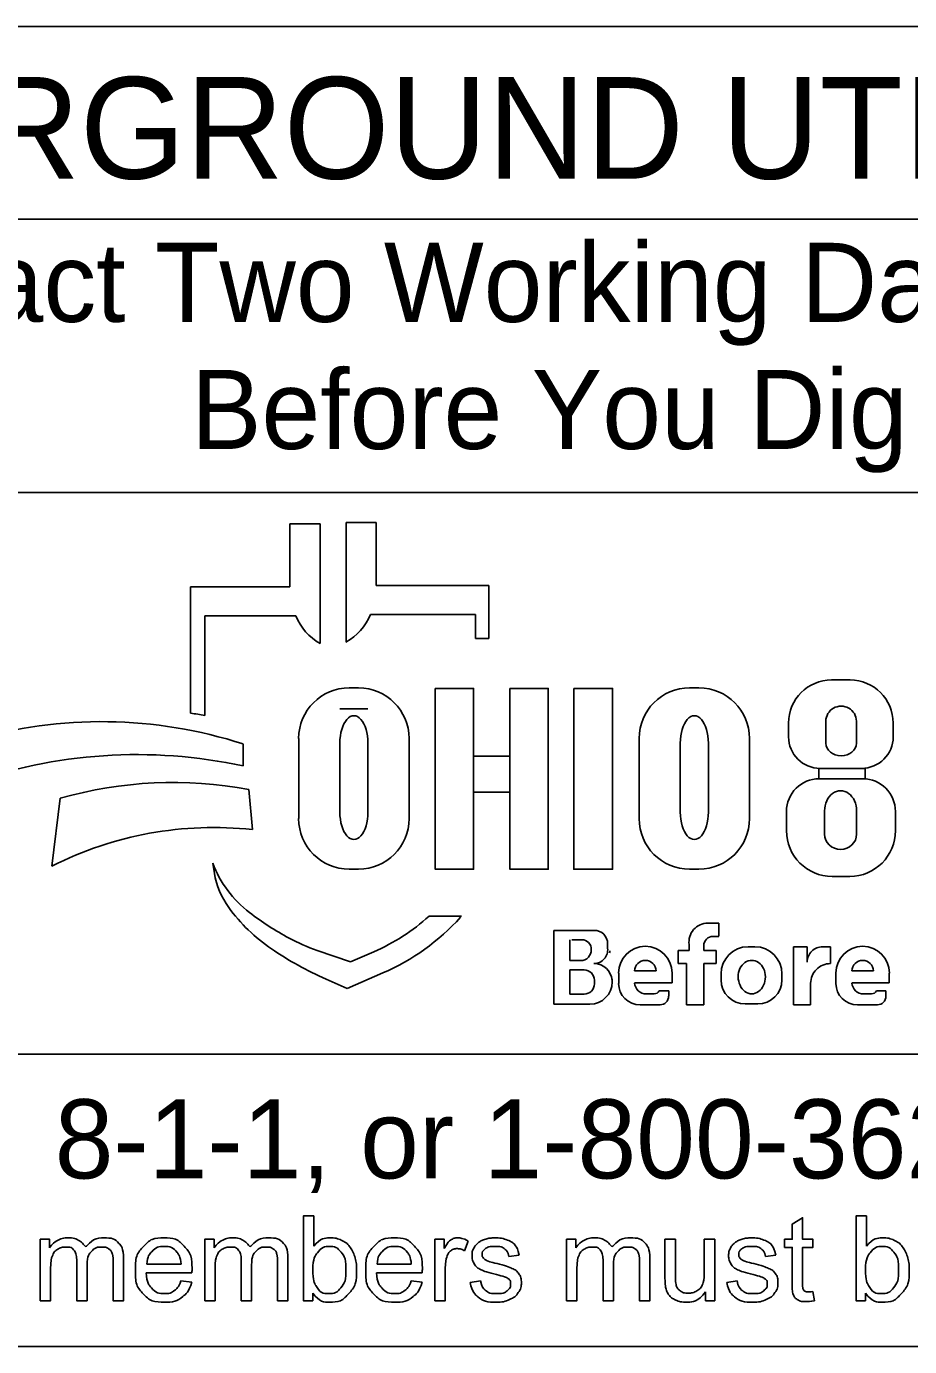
# Model space of a CAD drawing. Extents: x 0 to 34, y 0 to 22.
# Drawn here: x 3.267 to 4.831, y 2.143 to 4.48 of the extents above; entities that cross this region are included whole.
import ezdxf

# ---------------------------------------------------------------- set-up
doc = ezdxf.new("R2010")
doc.units = 0
doc.layers.add('SH_Data', color=7, linetype='Continuous')
doc.layers.add('SH_Text', color=7, linetype='Continuous')

msp = doc.modelspace()

# ---------------------------------------------------------------- linework, layer by layer
at = {"layer": 'SH_Data'}
for p, q in [((6.6275, 4.4803), (2.3775, 4.4803)), ((2.3775, 4.1387), (6.6275, 4.1387)), ((2.3775, 3.6553), (6.6275, 3.6553)), ((6.6275, 2.6607), (2.3775, 2.6607)), ((6.6275, 2.1428), (2.3775, 2.1428))]:
    msp.add_line(p, q, dxfattribs=at)
at = {"layer": 'SH_Text'}
for p, q in [((3.7335, 3.4883), (3.7335, 3.5998)), ((3.7335, 3.5998), (3.7872, 3.5998)), ((3.7872, 3.5998), (3.7872, 3.3877)), ((3.8329, 3.39), (3.8329, 3.6021)), ((3.8329, 3.6021), (3.8865, 3.6021)), ((3.8865, 3.6021), (3.8865, 3.4906)), ((3.5576, 3.2644), (3.5576, 3.4883)), ((3.5576, 3.4883), (3.7335, 3.4883)), ((3.8865, 3.4906), (4.0857, 3.4906)), ((4.0857, 3.4906), (4.0857, 3.3968)), ((3.5828, 3.4369), (3.5828, 3.26)), ((3.7439, 3.4369), (3.5828, 3.4369)), ((4.0625, 3.4392), (3.8761, 3.4392)), ((4.0625, 3.3968), (4.0625, 3.4392)), ((4.0857, 3.3968), (4.0625, 3.3968)), ((4.6931, 3.3231), (4.7258, 3.3231)), ((3.8385, 3.3091), (3.8551, 3.3091)), ((4.4416, 3.3091), (4.4581, 3.3091)), ((3.8718, 3.2721), (3.822, 3.2721)), ((4.683, 3.2111), (4.683, 3.2504)), ((4.7371, 3.2504), (4.7371, 3.2111)), ((4.6168, 3.2225), (4.6168, 3.2468)), ((4.8022, 3.2468), (4.8022, 3.2225)), ((3.6509, 3.2097), (3.6509, 3.1709)), ((3.7491, 3.0776), (3.7491, 3.2196)), ((3.822, 3.089), (3.822, 3.2114)), ((3.8718, 3.2114), (3.8718, 3.089)), ((3.9445, 3.2196), (3.9445, 3.0776)), ((4.3521, 3.0776), (4.3521, 3.2196)), ((4.425, 3.089), (4.425, 3.2114)), ((4.4748, 3.2114), (4.4748, 3.089)), ((4.5476, 3.2196), (4.5476, 3.0776)), ((4.7462, 3.1665), (4.6728, 3.1665)), ((4.671, 3.1482), (4.7483, 3.1482)), ((3.312, 2.9936), (3.3267, 3.1137)), ((3.6608, 3.1291), (3.6671, 3.0582)), ((4.6131, 3.0563), (4.6131, 3.0903)), ((4.6806, 3.0503), (4.6806, 3.0912)), ((4.7374, 3.0912), (4.7374, 3.0503)), ((4.8062, 3.0903), (4.8062, 3.0563)), ((3.5997, 2.9807), (3.5967, 2.9986)), ((3.8551, 2.9882), (3.8385, 2.9882)), ((4.4581, 2.9882), (4.4416, 2.9882)), ((4.7252, 2.9753), (4.6941, 2.9753)), ((3.98, 2.9048), (4.0375, 2.9048)), ((4.2013, 2.749), (4.2013, 2.8798)), ((4.2013, 2.8798), (4.2725, 2.8798)), ((4.4739, 2.8926), (4.4934, 2.8926)), ((4.4934, 2.8926), (4.4934, 2.8696)), ((4.2293, 2.8263), (4.2293, 2.8632)), ((4.2545, 2.8632), (4.2332, 2.8632)), ((4.2963, 2.856), (4.2963, 2.8481)), ((4.4406, 2.8442), (4.4406, 2.8546)), ((4.4667, 2.8526), (4.4667, 2.8442)), ((4.4934, 2.8691), (4.4832, 2.8691)), ((3.7816, 2.8444), (3.841, 2.8239)), ((3.841, 2.8239), (3.8821, 2.8417)), ((4.4213, 2.8212), (4.4213, 2.8442)), ((4.4213, 2.8442), (4.4406, 2.8442)), ((4.4667, 2.8442), (4.4883, 2.8442)), ((4.4883, 2.8442), (4.4883, 2.8212)), ((4.5451, 2.8508), (4.5573, 2.8508)), ((4.6254, 2.7478), (4.6254, 2.8505)), ((4.6254, 2.8505), (4.6499, 2.8505)), ((4.6499, 2.8505), (4.6499, 2.8237)), ((4.6772, 2.8505), (4.691, 2.8505)), ((4.691, 2.8505), (4.691, 2.8209)), ((4.2487, 2.8263), (4.2293, 2.8263)), ((4.2293, 2.7669), (4.2293, 2.8097)), ((4.2293, 2.8097), (4.2548, 2.8097)), ((4.3824, 2.8082), (4.3439, 2.8082)), ((4.4362, 2.8212), (4.4213, 2.8212)), ((4.4362, 2.7478), (4.4362, 2.8212)), ((4.4883, 2.8212), (4.4667, 2.8212)), ((4.4667, 2.8212), (4.4667, 2.7478)), ((4.7674, 2.8082), (4.7288, 2.8082)), ((3.835, 2.7769), (3.7976, 2.7934)), ((3.8983, 2.8044), (3.835, 2.7769)), ((4.2729, 2.7916), (4.2729, 2.7853)), ((4.3043, 2.7887), (4.3043, 2.7884)), ((4.3159, 2.7858), (4.3159, 2.8042)), ((4.4104, 2.7866), (4.344, 2.7866)), ((4.4104, 2.8042), (4.4104, 2.7866)), ((4.4973, 2.7922), (4.4973, 2.8029)), ((4.6051, 2.8029), (4.6051, 2.7922)), ((4.6559, 2.786), (4.6559, 2.7478)), ((4.7008, 2.7858), (4.7008, 2.8042)), ((4.7953, 2.7866), (4.7289, 2.7866)), ((4.7953, 2.8042), (4.7953, 2.7866)), ((4.2546, 2.7669), (4.2293, 2.7669)), ((4.3649, 2.7673), (4.379, 2.7673)), ((4.3876, 2.7729), (4.4045, 2.7729)), ((4.4045, 2.7729), (4.4045, 2.7631)), ((4.7498, 2.7673), (4.7639, 2.7673)), ((4.7725, 2.7729), (4.7894, 2.7729)), ((4.7894, 2.7729), (4.7894, 2.7631)), ((4.265, 2.749), (4.2013, 2.749)), ((4.3892, 2.7478), (4.3538, 2.7478)), ((4.4667, 2.7478), (4.4362, 2.7478)), ((4.5623, 2.7494), (4.5401, 2.7494)), ((4.6559, 2.7478), (4.6254, 2.7478)), ((4.7742, 2.7478), (4.7388, 2.7478))]:
    msp.add_line(p, q, dxfattribs=at)
for points in [[(3.991, 3.3081), (4.0589, 3.3081), (4.0589, 2.9881), (3.991, 2.9881)], [(4.1231, 3.3081), (4.1911, 3.3081), (4.1911, 2.9881), (4.1231, 2.9881)], [(4.2364, 3.3081), (4.3052, 3.3081), (4.3052, 2.9881), (4.2364, 2.9881)], [(4.0589, 3.1882), (4.1231, 3.1882), (4.1231, 3.1242), (4.0589, 3.1242)], [(4.6706, 3.1665), (4.7523, 3.1665), (4.7523, 3.1481), (4.6706, 3.1481)]]:
    msp.add_lwpolyline(points, close=True, dxfattribs=at)
for points in [[(3.7743, 2.2239), (3.7573, 2.2239), (3.7573, 2.3741), (3.7757, 2.3741), (3.7757, 2.3206)], [(4.6233, 2.2558), (4.6233, 2.3185), (4.6097, 2.3185), (4.6097, 2.3328), (4.6233, 2.3328), (4.6233, 2.3597), (4.6417, 2.3708), (4.6417, 2.3328), (4.6601, 2.3328), (4.6601, 2.3185), (4.6417, 2.3185), (4.6417, 2.2547)], [(4.7534, 2.2239), (4.7363, 2.2239), (4.7363, 2.3741), (4.7548, 2.3741), (4.7548, 2.3206)], [(3.2912, 2.2239), (3.2912, 2.3328), (3.3077, 2.3328), (3.3077, 2.3174)], [(3.5826, 2.2239), (3.5826, 2.3328), (3.5991, 2.3328), (3.5991, 2.3174)], [(3.9904, 2.2239), (3.9904, 2.3328), (4.007, 2.3328), (4.007, 2.3163)], [(4.0495, 2.3293), (4.043, 2.3122)], [(4.2236, 2.2239), (4.2236, 2.3328), (4.2401, 2.3328), (4.2401, 2.3174)], [(4.3979, 2.2654), (4.3979, 2.3328), (4.4164, 2.3328), (4.4164, 2.2724)], [(4.4676, 2.2745), (4.4676, 2.3328), (4.4861, 2.3328), (4.4861, 2.2239), (4.4696, 2.2239)], [(3.3743, 2.2871), (3.3743, 2.2239), (3.3559, 2.2239), (3.3559, 2.2946)], [(3.4388, 2.2986), (3.4388, 2.2239), (3.4203, 2.2239), (3.4203, 2.2924)], [(3.6657, 2.2871), (3.6657, 2.2239), (3.6473, 2.2239), (3.6473, 2.2946)], [(3.7301, 2.2986), (3.7301, 2.2239), (3.7117, 2.2239), (3.7117, 2.2924)], [(4.1394, 2.3046), (4.1213, 2.3022)], [(4.3067, 2.2871), (4.3067, 2.2239), (4.2883, 2.2239), (4.2883, 2.2946)], [(4.3711, 2.2986), (4.3711, 2.2239), (4.3527, 2.2239), (4.3527, 2.2924)], [(4.594, 2.3046), (4.5759, 2.3022)], [(3.3097, 2.2803), (3.3097, 2.2239), (3.2912, 2.2239)], [(3.56, 2.2736), (3.4788, 2.2736)], [(3.4799, 2.2887), (3.5406, 2.2887)], [(3.601, 2.2803), (3.601, 2.2239), (3.5826, 2.2239)], [(3.968, 2.2736), (3.8868, 2.2736)], [(3.8879, 2.2887), (3.9486, 2.2887)], [(4.0088, 2.2809), (4.0088, 2.2239), (3.9904, 2.2239)], [(4.242, 2.2803), (4.242, 2.2239), (4.2236, 2.2239)], [(3.5404, 2.2591), (3.5595, 2.2567)], [(3.9484, 2.2591), (3.9675, 2.2567)], [(4.053, 2.2564), (4.0712, 2.2593)], [(4.5076, 2.2564), (4.5258, 2.2593)], [(3.7743, 2.2375), (3.7743, 2.2239)], [(4.4696, 2.2239), (4.4696, 2.24)], [(4.6601, 2.2404), (4.6628, 2.2241)], [(4.7534, 2.2375), (4.7534, 2.2239)]]:
    msp.add_lwpolyline(points, dxfattribs=at)
for centre, radius, start, end in [((3.8353, 3.4736), 0.0985, 201.9296, 240.7469), ((3.7847, 3.476), 0.0985, 299.2531, 338.0704), ((4.6931, 3.2468), 0.0763, 90, 180), ((4.7258, 3.2468), 0.0763, 0, 90), ((3.8385, 3.2196), 0.0895, 90, 180), ((3.8551, 3.2196), 0.0895, 0, 90), ((4.4416, 3.2196), 0.0895, 90, 180), ((4.4581, 3.2196), 0.0895, 0, 90), ((3.3997, 2.4302), 0.8191, 72.1402, 106.3144), ((3.4295, 2.4554), 0.8191, 79.2074, 81.0007), ((4.6728, 3.2225), 0.056, 180, 270), ((4.7462, 3.2225), 0.056, 270, 0), ((3.4628, 2.2991), 0.8919, 77.8238, 109.8274), ((3.5267, 2.4094), 0.7322, 79.44, 105.8467), ((4.671, 3.0903), 0.0579, 90, 180), ((4.7483, 3.0903), 0.0579, 0, 90), ((3.8385, 3.0776), 0.0895, 180, 270), ((3.8551, 3.0776), 0.0895, 270, 0), ((4.4416, 3.0776), 0.0895, 180, 270), ((4.4581, 3.0776), 0.0895, 270, 0), ((3.5987, 2.4262), 0.6357, 83.8248, 116.8021), ((4.6941, 3.0563), 0.081, 180, 270), ((4.7252, 3.0563), 0.081, 270, 0), ((3.7841, 3.0707), 0.2008, 201.0457, 232.5314), ((3.741, 3.0048), 0.1433, 189.6817, 216.0884), ((3.8747, 3.1022), 0.3088, 216.0884, 235.7167), ((3.9766, 3.3219), 0.5173, 232.5314, 241.794), ((3.7387, 3.1722), 0.3602, 293.4582, 312.0712), ((3.7387, 3.1722), 0.401, 293.4582, 317.8286), ((4.2725, 2.856), 0.0238, 0, 90), ((4.4739, 2.859), 0.0335, 90, 187.5187), ((3.8914, 3.1631), 0.3371, 241.794, 250.9821), ((4.2505, 2.8463), 0.0169, 357.8325, 90), ((4.4832, 2.8526), 0.0165, 90, 180), ((4.0412, 3.3465), 0.6044, 235.7167, 246.2325), ((4.2487, 2.845), 0.0187, 270, 2.0582), ((4.2721, 2.8453), 0.0243, 270, 6.6529), ((4.2827, 2.8438), 0.0175, 347.4023, 0), ((4.3631, 2.8042), 0.0473, 0, 180), ((4.5451, 2.8029), 0.0478, 90, 180), ((4.5573, 2.8029), 0.0478, 0, 90), ((4.6768, 2.8237), 0.0269, 89.2449, 180), ((4.7481, 2.8042), 0.0473, 0, 180), ((4.2548, 2.7916), 0.0181, 0, 90), ((4.2722, 2.7889), 0.0321, 4.0748, 90), ((4.3632, 2.8072), 0.0193, 2.9632, 177.0368), ((4.6908, 2.786), 0.0349, 89.6033, 180), ((4.7481, 2.8072), 0.0193, 2.9632, 177.0368), ((4.2546, 2.7853), 0.0184, 270, 0), ((4.265, 2.7884), 0.0393, 270, 0), ((4.2714, 2.7887), 0.033, 0, 11.7502), ((4.3538, 2.7858), 0.038, 180, 270), ((4.3649, 2.7883), 0.021, 184.827, 270), ((4.5401, 2.7922), 0.0428, 180, 270), ((4.5623, 2.7922), 0.0428, 270, 0), ((4.7388, 2.7858), 0.038, 180, 270), ((4.7498, 2.7883), 0.021, 184.827, 270), ((4.379, 2.7767), 0.00938, 270, 335.9979), ((4.3892, 2.7631), 0.0152, 270, 0), ((4.7639, 2.7767), 0.00938, 270, 335.9979), ((4.7742, 2.7631), 0.0152, 270, 0)]:
    msp.add_arc(centre, radius, start, end, dxfattribs=at)
for centre, major_axis, ratio, start_param, end_param in [((4.71, 3.2504), (0.0271, 0), 0.969373, 0, 3.141593), ((3.8469, 3.2114), (0, 0.0484), 0.514403, 4.712389, 7.853982), ((4.4499, 3.2114), (0, 0.0484), 0.514403, 4.712389, 7.853982), ((4.71, 3.2111), (0.0271, 0), 0.818453, 3.141593, 6.283185), ((4.709, 3.0912), (0, 0.0358), 0.794529, 4.712389, 7.853982), ((3.8469, 3.089), (0, 0.0484), 0.514403, 1.570796, 4.712389), ((4.4499, 3.089), (0, 0.0484), 0.514403, 1.570796, 4.712389), ((4.709, 3.0503), (0.0284, 0), 0.959837, 3.141593, 6.283185), ((4.5517, 2.7976), (0, 0.029), 0.832186, 4.712389, 7.853982), ((4.5517, 2.7976), (0, 0.0302), 0.797287, 1.570796, 4.712389)]:
    msp.add_ellipse(centre, major_axis=major_axis, ratio=ratio, start_param=start_param, end_param=end_param, dxfattribs=at)
for points in [[(3.3077, 2.3174), (3.3128, 2.3254), (3.3214, 2.3303), (3.3299, 2.3352), (3.3407, 2.3352), (3.3528, 2.3352), (3.3606, 2.3301), (3.3683, 2.3251), (3.3715, 2.3161), (3.3844, 2.3352), (3.4051, 2.3352), (3.4213, 2.3352), (3.43, 2.3262), (3.4388, 2.3172), (3.4388, 2.2986)], [(3.3559, 2.2946), (3.3559, 2.3069), (3.3514, 2.313), (3.3469, 2.3191), (3.3366, 2.3191), (3.3288, 2.3191), (3.3222, 2.315), (3.3156, 2.311), (3.3126, 2.3031), (3.3097, 2.2952), (3.3097, 2.2803)], [(3.4203, 2.2924), (3.4203, 2.3035), (3.4185, 2.3083), (3.4168, 2.3132), (3.412, 2.3162), (3.4073, 2.3191), (3.401, 2.3191), (3.3895, 2.3191), (3.3819, 2.3115), (3.3743, 2.3039), (3.3743, 2.2871)], [(3.5595, 2.2567), (3.555, 2.24), (3.5428, 2.2307), (3.5306, 2.2215), (3.5117, 2.2215), (3.4878, 2.2215), (3.4738, 2.2362), (3.4598, 2.2509), (3.4598, 2.2774), (3.4598, 2.3049), (3.474, 2.32), (3.4881, 2.3352), (3.5106, 2.3352), (3.5324, 2.3352), (3.5463, 2.3203), (3.5601, 2.3055), (3.5601, 2.2785), (3.5601, 2.2769), (3.56, 2.2736)], [(3.5406, 2.2887), (3.5394, 2.3025), (3.5337, 2.3094), (3.5249, 2.3201), (3.5108, 2.3201), (3.4981, 2.3201), (3.4894, 2.3115), (3.4808, 2.303), (3.4799, 2.2887)], [(3.5991, 2.3174), (3.6042, 2.3254), (3.6127, 2.3303), (3.6212, 2.3352), (3.6321, 2.3352), (3.6442, 2.3352), (3.6519, 2.3301), (3.6597, 2.3251), (3.6628, 2.3161), (3.6758, 2.3352), (3.6965, 2.3352), (3.7127, 2.3352), (3.7214, 2.3262), (3.7301, 2.3172), (3.7301, 2.2986)], [(3.6473, 2.2946), (3.6473, 2.3069), (3.6428, 2.313), (3.6383, 2.3191), (3.628, 2.3191), (3.6202, 2.3191), (3.6136, 2.315), (3.607, 2.311), (3.604, 2.3031), (3.601, 2.2952), (3.601, 2.2803)], [(3.7117, 2.2924), (3.7117, 2.3035), (3.7099, 2.3083), (3.7081, 2.3132), (3.7034, 2.3162), (3.6987, 2.3191), (3.6923, 2.3191), (3.6809, 2.3191), (3.6733, 2.3115), (3.6657, 2.3039), (3.6657, 2.2871)], [(3.7741, 2.2792), (3.7741, 2.2596), (3.7794, 2.2509), (3.7881, 2.2366), (3.8029, 2.2366), (3.815, 2.2366), (3.8238, 2.2471), (3.8326, 2.2576), (3.8326, 2.2784), (3.8326, 2.2998), (3.8241, 2.3099), (3.8157, 2.3201), (3.8038, 2.3201), (3.7917, 2.3201), (3.7829, 2.3096), (3.7741, 2.299), (3.7741, 2.2792)], [(3.7757, 2.3206), (3.7874, 2.3352), (3.8055, 2.3352), (3.8155, 2.3352), (3.8245, 2.3311), (3.8335, 2.3271), (3.8392, 2.3198), (3.845, 2.3124), (3.8483, 2.3021), (3.8516, 2.2918), (3.8516, 2.28), (3.8516, 2.252), (3.8378, 2.2368), (3.8239, 2.2215), (3.8046, 2.2215), (3.7853, 2.2215), (3.7743, 2.2375)], [(3.9675, 2.2567), (3.963, 2.24), (3.9508, 2.2307), (3.9386, 2.2215), (3.9196, 2.2215), (3.8958, 2.2215), (3.8818, 2.2362), (3.8678, 2.2509), (3.8678, 2.2774), (3.8678, 2.3049), (3.882, 2.32), (3.8961, 2.3352), (3.9186, 2.3352), (3.9404, 2.3352), (3.9543, 2.3203), (3.9681, 2.3055), (3.9681, 2.2785), (3.9681, 2.2769), (3.968, 2.2736)], [(3.9486, 2.2887), (3.9474, 2.3025), (3.9417, 2.3094), (3.9328, 2.3201), (3.9188, 2.3201), (3.9061, 2.3201), (3.8974, 2.3115), (3.8888, 2.303), (3.8879, 2.2887)], [(4.007, 2.3163), (4.0133, 2.3278), (4.0187, 2.3315), (4.0241, 2.3352), (4.0305, 2.3352), (4.0398, 2.3352), (4.0495, 2.3293)], [(4.043, 2.3122), (4.0363, 2.3162), (4.0295, 2.3162), (4.0235, 2.3162), (4.0187, 2.3125), (4.0139, 2.3089), (4.0119, 2.3024), (4.0088, 2.2926), (4.0088, 2.2809)], [(4.1213, 2.3022), (4.1201, 2.3106), (4.1142, 2.3153), (4.1083, 2.3201), (4.0975, 2.3201), (4.0848, 2.3201), (4.0794, 2.3159), (4.0739, 2.3116), (4.0739, 2.306), (4.0739, 2.3024), (4.0762, 2.2995), (4.0785, 2.2966), (4.0833, 2.2946), (4.086, 2.2936), (4.0996, 2.2899), (4.1192, 2.2847), (4.1269, 2.2813), (4.1347, 2.278), (4.1391, 2.2717), (4.1435, 2.2653), (4.1435, 2.2559), (4.1435, 2.2467), (4.1381, 2.2386), (4.1327, 2.2304), (4.1226, 2.226), (4.1124, 2.2215), (4.0996, 2.2215), (4.0784, 2.2215), (4.0672, 2.2303), (4.0561, 2.2391), (4.053, 2.2564)], [(4.0712, 2.2593), (4.0727, 2.2483), (4.0798, 2.2425), (4.0868, 2.2366), (4.0995, 2.2366), (4.1122, 2.2366), (4.1184, 2.2418), (4.1245, 2.247), (4.1245, 2.254), (4.1245, 2.2602), (4.1191, 2.2638), (4.1153, 2.2663), (4.1002, 2.2701), (4.0799, 2.2752), (4.072, 2.2789), (4.0642, 2.2827), (4.0601, 2.2893), (4.0561, 2.2959), (4.0561, 2.3038), (4.0561, 2.3111), (4.0594, 2.3173), (4.0628, 2.3235), (4.0685, 2.3276), (4.0728, 2.3308), (4.0803, 2.333), (4.0877, 2.3352), (4.0962, 2.3352), (4.109, 2.3352), (4.1187, 2.3315), (4.1284, 2.3278), (4.133, 2.3215), (4.1377, 2.3152), (4.1394, 2.3046)], [(4.2401, 2.3174), (4.2452, 2.3254), (4.2537, 2.3303), (4.2622, 2.3352), (4.2731, 2.3352), (4.2852, 2.3352), (4.2929, 2.3301), (4.3007, 2.3251), (4.3038, 2.3161), (4.3168, 2.3352), (4.3375, 2.3352), (4.3537, 2.3352), (4.3624, 2.3262), (4.3711, 2.3172), (4.3711, 2.2986)], [(4.2883, 2.2946), (4.2883, 2.3069), (4.2838, 2.313), (4.2793, 2.3191), (4.269, 2.3191), (4.2612, 2.3191), (4.2546, 2.315), (4.248, 2.311), (4.245, 2.3031), (4.242, 2.2952), (4.242, 2.2803)], [(4.3527, 2.2924), (4.3527, 2.3035), (4.3509, 2.3083), (4.3491, 2.3132), (4.3444, 2.3162), (4.3397, 2.3191), (4.3333, 2.3191), (4.3219, 2.3191), (4.3143, 2.3115), (4.3067, 2.3039), (4.3067, 2.2871)], [(4.5759, 2.3022), (4.5747, 2.3106), (4.5688, 2.3153), (4.5629, 2.3201), (4.5521, 2.3201), (4.5394, 2.3201), (4.5339, 2.3159), (4.5285, 2.3116), (4.5285, 2.306), (4.5285, 2.3024), (4.5308, 2.2995), (4.533, 2.2966), (4.5378, 2.2946), (4.5406, 2.2936), (4.5542, 2.2899), (4.5737, 2.2847), (4.5815, 2.2813), (4.5893, 2.278), (4.5937, 2.2717), (4.5981, 2.2653), (4.5981, 2.2559), (4.5981, 2.2467), (4.5927, 2.2386), (4.5873, 2.2304), (4.5772, 2.226), (4.567, 2.2215), (4.5542, 2.2215), (4.5329, 2.2215), (4.5218, 2.2303), (4.5107, 2.2391), (4.5076, 2.2564)], [(4.5258, 2.2593), (4.5273, 2.2483), (4.5343, 2.2425), (4.5414, 2.2366), (4.554, 2.2366), (4.5668, 2.2366), (4.5729, 2.2418), (4.5791, 2.247), (4.5791, 2.254), (4.5791, 2.2602), (4.5736, 2.2638), (4.5698, 2.2663), (4.5548, 2.2701), (4.5345, 2.2752), (4.5266, 2.2789), (4.5188, 2.2827), (4.5147, 2.2893), (4.5107, 2.2959), (4.5107, 2.3038), (4.5107, 2.3111), (4.514, 2.3173), (4.5173, 2.3235), (4.5231, 2.3276), (4.5274, 2.3308), (4.5348, 2.333), (4.5423, 2.3352), (4.5508, 2.3352), (4.5636, 2.3352), (4.5733, 2.3315), (4.583, 2.3278), (4.5876, 2.3215), (4.5922, 2.3152), (4.594, 2.3046)], [(4.7532, 2.2792), (4.7532, 2.2596), (4.7585, 2.2509), (4.7672, 2.2366), (4.782, 2.2366), (4.7941, 2.2366), (4.8029, 2.2471), (4.8116, 2.2576), (4.8116, 2.2784), (4.8116, 2.2998), (4.8032, 2.3099), (4.7948, 2.3201), (4.7828, 2.3201), (4.7708, 2.3201), (4.762, 2.3096), (4.7532, 2.299), (4.7532, 2.2792)], [(4.7548, 2.3206), (4.7664, 2.3352), (4.7846, 2.3352), (4.7946, 2.3352), (4.8036, 2.3311), (4.8125, 2.3271), (4.8183, 2.3198), (4.8241, 2.3124), (4.8274, 2.3021), (4.8306, 2.2918), (4.8306, 2.28), (4.8306, 2.252), (4.8168, 2.2368), (4.803, 2.2215), (4.7836, 2.2215), (4.7644, 2.2215), (4.7534, 2.2375)], [(3.4788, 2.2736), (3.4799, 2.2557), (3.489, 2.2462), (3.4981, 2.2366), (3.5117, 2.2366), (3.5219, 2.2366), (3.5291, 2.242), (3.5362, 2.2473), (3.5404, 2.2591)], [(3.8868, 2.2736), (3.8879, 2.2557), (3.897, 2.2462), (3.9061, 2.2366), (3.9197, 2.2366), (3.9299, 2.2366), (3.937, 2.242), (3.9442, 2.2473), (3.9484, 2.2591)], [(4.4164, 2.2724), (4.4164, 2.258), (4.4175, 2.253), (4.4192, 2.2457), (4.4249, 2.2416), (4.4305, 2.2374), (4.4388, 2.2374), (4.4471, 2.2374), (4.4543, 2.2417), (4.4616, 2.2459), (4.4646, 2.2533), (4.4676, 2.2606), (4.4676, 2.2745)], [(4.4696, 2.24), (4.4569, 2.2215), (4.4351, 2.2215), (4.4255, 2.2215), (4.4171, 2.2252), (4.4088, 2.2289), (4.4047, 2.2345), (4.4007, 2.2401), (4.3991, 2.2482), (4.3979, 2.2536), (4.3979, 2.2654)], [(4.6628, 2.2241), (4.655, 2.2224), (4.6488, 2.2224), (4.6388, 2.2224), (4.6333, 2.2256), (4.6278, 2.2288), (4.6255, 2.234), (4.6233, 2.2392), (4.6233, 2.2558)], [(4.6417, 2.2547), (4.6417, 2.2468), (4.6427, 2.2445), (4.6436, 2.2423), (4.6458, 2.2409), (4.648, 2.2396), (4.6521, 2.2396), (4.6551, 2.2396), (4.6601, 2.2404)]]:
    msp.add_open_spline(points, degree=3, dxfattribs=at)

# ---------------------------------------------------------------- texts
for s, height, p in [('UNDERGROUND UTILITIES', 0.18, (2.5057, 4.2106)), ('Contact Two Working Days', 0.14, (2.7972, 3.9571)), ('Before You Dig', 0.14, (3.5583, 3.7321)), ('OHIO811, 8-1-1, or 1-800-362-2764', 0.14, (2.422, 2.4406))]:
    msp.add_text(s, height=height, dxfattribs=at).set_placement(p)

doc.saveas('drawing.dxf')
